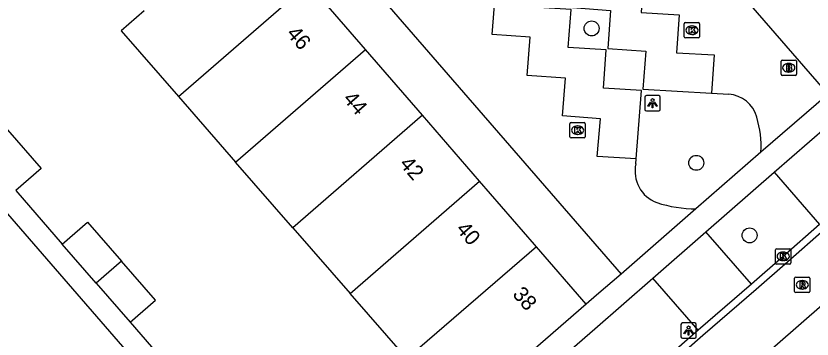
# Model space of a CAD drawing. Extents: x 155888 to 156864, y 383882 to 384671.
# Drawn here: x 156320.3 to 156372.4, y 384088.8 to 384110 of the extents above; entities that cross this region are included whole.
import ezdxf

# ---------------------------------------------------------------- set-up
doc = ezdxf.new("R2010")
doc.units = 0
for name, color, linetype in [('IMGEO_Boom', 7, 'Continuous'), ('IMGEO_Brandkraan', 7, 'Continuous'), ('IMGEO_Kolk', 7, 'Continuous'), ('IMGEO_Lichtpunt', 7, 'Continuous'), ('IMGEO_Pand', 7, 'Continuous'), ('IMGEO_Pand_nummerreeks', 7, 'Continuous'), ('IMGEO_Parkeervlak_open', 7, 'Continuous'), ('IMGEO_Rijbaan_lokaal_gesloten', 7, 'Continuous'), ('IMGEO_Rijbaan_lokaal_open', 7, 'Continuous'), ('IMGEO_Rioolput', 7, 'Continuous'), ('IMGEO_Voetpad_open', 7, 'Continuous')]:
    doc.layers.add(name, color=color, linetype=linetype)

msp = doc.modelspace()

# ---------------------------------------------------------------- linework, layer by layer
at = {"layer": 'IMGEO_Boom'}
for centre in [(156357.971, 384109.154), (156364.816, 384100.364), (156368.307, 384095.623)]:
    msp.add_circle(centre, 0.489, dxfattribs=at)
at = {"layer": 'IMGEO_Brandkraan'}
for p, q in [((156370.445, 384107.086), (156371.297, 384107.086)), ((156370.37, 384106.16), (156370.37, 384107.012)), ((156370.858, 384106.866), (156370.883, 384106.866)), ((156371.371, 384107.012), (156371.371, 384106.16)), ((156371.297, 384106.086), (156370.445, 384106.086)), ((156370.881, 384106.306), (156370.856, 384106.306))]:
    msp.add_line(p, q, dxfattribs=at)
for points in [[(156370.445, 384107.086), (156371.297, 384107.086)], [(156370.37, 384106.16), (156370.37, 384107.012)], [(156370.718, 384106.786), (156370.718, 384106.386), (156370.931, 384106.386)], [(156370.949, 384106.786), (156370.718, 384106.786)], [(156370.897, 384106.705), (156370.843, 384106.705), (156370.843, 384106.629)], [(156370.843, 384106.629), (156370.896, 384106.629)], [(156371.371, 384107.012), (156371.371, 384106.16)], [(156371.297, 384106.086), (156370.445, 384106.086)], [(156370.905, 384106.553), (156370.843, 384106.553), (156370.843, 384106.472)], [(156370.843, 384106.472), (156370.905, 384106.472)]]:
    msp.add_lwpolyline(points, dxfattribs=at)
for centre, radius, start, end in [((156370.447, 384107.01), 0.0765, 91.552, 178.448), ((156370.447, 384107.01), 0.0765, 91.552, 178.448), ((156371.295, 384107.01), 0.0765, 1.552, 88.448), ((156371.295, 384107.01), 0.0765, 1.552, 88.448), ((156370.898, 384106.667), 0.0379, 267.8285, 90.9355), ((156370.953, 384106.641), 0.145, 59.4692, 91.5367), ((156370.978, 384106.688), 0.0922, 285.5137, 58.1501), ((156370.983, 384106.496), 0.105, 301.3115, 78.989), ((156370.447, 384106.162), 0.0765, 181.552, 268.448), ((156370.447, 384106.162), 0.0765, 181.552, 268.448), ((156370.906, 384106.512), 0.0404, 269.8759, 90.5077), ((156370.937, 384106.637), 0.251, 268.6676, 293.5347), ((156371.295, 384106.162), 0.0765, 271.552, 358.448), ((156371.295, 384106.162), 0.0765, 271.552, 358.448)]:
    msp.add_arc(centre, radius, start, end, dxfattribs=at)
for centre, major_axis, ratio, start_param, end_param in [((156370.857, 384106.586), (-0.387, 0.002), 0.722429, 4.712389, 7.853982), ((156370.882, 384106.586), (-0.39, 0.002), 0.717154, 1.570796, 4.712389)]:
    msp.add_ellipse(centre, major_axis=major_axis, ratio=ratio, start_param=start_param, end_param=end_param, dxfattribs=at)
at = {"layer": 'IMGEO_Kolk'}
for p, q in [((156364.036, 384108.614), (156364.036, 384109.466)), ((156364.111, 384109.54), (156364.963, 384109.54)), ((156364.524, 384109.32), (156364.549, 384109.32)), ((156365.037, 384109.466), (156365.037, 384108.614)), ((156364.547, 384108.76), (156364.522, 384108.76)), ((156364.963, 384108.54), (156364.111, 384108.54)), ((156356.552, 384102.075), (156356.552, 384102.927)), ((156356.627, 384103.001), (156357.479, 384103.001)), ((156357.553, 384102.927), (156357.553, 384102.075)), ((156357.04, 384102.781), (156357.065, 384102.781)), ((156357.479, 384102.001), (156356.627, 384102.001)), ((156357.063, 384102.221), (156357.038, 384102.221)), ((156370.008, 384093.821), (156370.008, 384094.673)), ((156370.083, 384094.747), (156370.935, 384094.747)), ((156371.009, 384094.673), (156371.009, 384093.821)), ((156370.496, 384094.527), (156370.521, 384094.527)), ((156370.935, 384093.747), (156370.083, 384093.747)), ((156370.519, 384093.967), (156370.494, 384093.967))]:
    msp.add_line(p, q, dxfattribs=at)
for points in [[(156364.036, 384108.614), (156364.036, 384109.466)], [(156364.111, 384109.54), (156364.963, 384109.54)], [(156364.357, 384109.24), (156364.48, 384109.24), (156364.48, 384109.089), (156364.61, 384109.24), (156364.774, 384109.24), (156364.628, 384109.089), (156364.781, 384108.84), (156364.629, 384108.84), (156364.544, 384109.004), (156364.48, 384108.937), (156364.48, 384108.84), (156364.357, 384108.84), (156364.357, 384109.24)], [(156365.037, 384109.466), (156365.037, 384108.614)], [(156364.963, 384108.54), (156364.111, 384108.54)], [(156356.552, 384102.075), (156356.552, 384102.927)], [(156356.627, 384103.001), (156357.479, 384103.001)], [(156357.553, 384102.927), (156357.553, 384102.075)], [(156356.873, 384102.701), (156356.996, 384102.701), (156356.996, 384102.55), (156357.126, 384102.701), (156357.29, 384102.701), (156357.144, 384102.55), (156357.297, 384102.301), (156357.145, 384102.301), (156357.06, 384102.465), (156356.996, 384102.398), (156356.996, 384102.301), (156356.873, 384102.301), (156356.873, 384102.701)], [(156357.479, 384102.001), (156356.627, 384102.001)], [(156370.008, 384093.821), (156370.008, 384094.673)], [(156370.083, 384094.747), (156370.935, 384094.747)], [(156371.009, 384094.673), (156371.009, 384093.821)], [(156370.329, 384094.447), (156370.452, 384094.447), (156370.452, 384094.296), (156370.582, 384094.447), (156370.746, 384094.447), (156370.6, 384094.296), (156370.753, 384094.047), (156370.601, 384094.047), (156370.516, 384094.211), (156370.452, 384094.144), (156370.452, 384094.047), (156370.329, 384094.047), (156370.329, 384094.447)], [(156370.935, 384093.747), (156370.083, 384093.747)]]:
    msp.add_lwpolyline(points, dxfattribs=at)
for centre, start, end in [((156364.113, 384109.464), 91.552, 178.448), ((156364.113, 384109.464), 91.552, 178.448), ((156364.961, 384109.464), 1.552, 88.448), ((156364.961, 384109.464), 1.552, 88.448), ((156364.113, 384108.616), 181.552, 268.448), ((156364.113, 384108.616), 181.552, 268.448), ((156364.961, 384108.616), 271.552, 358.448), ((156364.961, 384108.616), 271.552, 358.448), ((156356.629, 384102.925), 91.552, 178.448), ((156356.629, 384102.925), 91.552, 178.448), ((156357.477, 384102.925), 1.552, 88.448), ((156357.477, 384102.925), 1.552, 88.448), ((156356.629, 384102.077), 181.552, 268.448), ((156356.629, 384102.077), 181.552, 268.448), ((156357.477, 384102.077), 271.552, 358.448), ((156357.477, 384102.077), 271.552, 358.448), ((156370.085, 384094.671), 91.552, 178.448), ((156370.085, 384094.671), 91.552, 178.448), ((156370.933, 384094.671), 1.552, 88.448), ((156370.933, 384094.671), 1.552, 88.448), ((156370.085, 384093.823), 181.552, 268.448), ((156370.085, 384093.823), 181.552, 268.448), ((156370.933, 384093.823), 271.552, 358.448), ((156370.933, 384093.823), 271.552, 358.448)]:
    msp.add_arc(centre, 0.0765, start, end, dxfattribs=at)
for centre, major_axis, ratio, start_param, end_param in [((156364.523, 384109.04), (-0.387, 0.002), 0.722429, 4.712389, 7.853982), ((156364.548, 384109.04), (-0.39, 0.002), 0.717154, 1.570796, 4.712389), ((156357.039, 384102.501), (-0.387, 0.002), 0.722429, 4.712389, 7.853982), ((156357.064, 384102.501), (-0.39, 0.002), 0.717154, 1.570796, 4.712389), ((156370.495, 384094.247), (-0.387, 0.002), 0.722429, 4.712389, 7.853982), ((156370.52, 384094.247), (-0.39, 0.002), 0.717154, 1.570796, 4.712389)]:
    msp.add_ellipse(centre, major_axis=major_axis, ratio=ratio, start_param=start_param, end_param=end_param, dxfattribs=at)
at = {"layer": 'IMGEO_Lichtpunt'}
for p, q in [((156361.457, 384104.668), (156361.457, 384103.861)), ((156361.457, 384104.668), (156361.457, 384103.861)), ((156362.359, 384104.763), (156361.551, 384104.763)), ((156362.359, 384104.763), (156361.551, 384104.763)), ((156362.453, 384103.861), (156362.453, 384104.668)), ((156362.453, 384103.861), (156362.453, 384104.668)), ((156361.551, 384103.767), (156362.359, 384103.767)), ((156361.551, 384103.767), (156362.359, 384103.767)), ((156364.718, 384089.895), (156363.91, 384089.895)), ((156364.718, 384089.895), (156363.91, 384089.895)), ((156363.816, 384089.8), (156363.816, 384088.993)), ((156363.816, 384089.8), (156363.816, 384088.993)), ((156364.812, 384088.993), (156364.812, 384089.8)), ((156364.812, 384088.993), (156364.812, 384089.8)), ((156363.91, 384088.899), (156364.718, 384088.899)), ((156363.91, 384088.899), (156364.718, 384088.899))]:
    msp.add_line(p, q, dxfattribs=at)
for points in [[(156361.831, 384104.332), (156361.87, 384104.304), (156361.682, 384104.042), (156361.644, 384104.069), (156361.831, 384104.332)], [(156361.933, 384104.284), (156361.98, 384104.284), (156361.98, 384103.962), (156361.933, 384103.962), (156361.933, 384104.284)], [(156362.043, 384104.304), (156362.081, 384104.331), (156362.268, 384104.069), (156362.229, 384104.041), (156362.043, 384104.304)], [(156364.19, 384089.464), (156364.229, 384089.436), (156364.041, 384089.174), (156364.003, 384089.201), (156364.19, 384089.464)], [(156364.292, 384089.416), (156364.339, 384089.416), (156364.339, 384089.094), (156364.292, 384089.094), (156364.292, 384089.416)], [(156364.402, 384089.436), (156364.44, 384089.463), (156364.627, 384089.201), (156364.588, 384089.173), (156364.402, 384089.436)]]:
    msp.add_lwpolyline(points, dxfattribs=at)
for centre in [(156361.956, 384104.466), (156364.315, 384089.598)]:
    msp.add_circle(centre, 0.0994, dxfattribs=at)
for centre, start, end in [((156361.551, 384104.668), 90, 180), ((156361.551, 384104.668), 90, 180), ((156362.359, 384104.668), 0, 90), ((156362.359, 384104.668), 0, 90), ((156361.551, 384103.861), 180, 270), ((156361.551, 384103.861), 180, 270), ((156362.359, 384103.861), 270, 0), ((156362.359, 384103.861), 270, 360), ((156363.91, 384089.8), 90, 180), ((156363.91, 384089.8), 90, 180), ((156364.718, 384089.8), 0, 90), ((156364.718, 384089.8), 0, 90), ((156363.91, 384088.993), 180, 270), ((156363.91, 384088.993), 180, 270), ((156364.718, 384088.993), 270, 0), ((156364.718, 384088.993), 270, 360)]:
    msp.add_arc(centre, 0.0946, start, end, dxfattribs=at)
at = {"layer": 'IMGEO_Pand'}
for points in [[(156330.929, 384104.7), (156339.43, 384112.085)], [(156343.163, 384107.781), (156339.43, 384112.085)], [(156328.695, 384110.304), (156327.186, 384108.993), (156330.929, 384104.7)], [(156334.671, 384100.407), (156343.163, 384107.781)], [(156346.896, 384103.477), (156343.163, 384107.781)], [(156330.929, 384104.7), (156334.671, 384100.407)], [(156346.896, 384103.477), (156338.413, 384096.115)], [(156350.629, 384099.174), (156346.896, 384103.477)], [(156319.75, 384102.532), (156321.949, 384099.997), (156320.29, 384098.559)], [(156338.413, 384096.115), (156334.671, 384100.407)], [(156342.157, 384091.821), (156350.629, 384099.174)], [(156354.362, 384094.871), (156354.231, 384095.022), (156350.629, 384099.174)], [(156323.327, 384095.056), (156324.982, 384096.491), (156327.207, 384093.926)], [(156338.413, 384096.115), (156342.157, 384091.821)], [(156325.552, 384092.489), (156323.326, 384095.055), (156323.327, 384095.056)], [(156354.362, 384094.871), (156344.503, 384086.363)], [(156357.607, 384091.13), (156354.362, 384094.871)], [(156327.207, 384093.926), (156325.552, 384092.489)], [(156327.766, 384089.938), (156329.421, 384091.373), (156327.207, 384093.926)], [(156325.552, 384092.489), (156327.766, 384089.938)], [(156344.503, 384086.363), (156344.387, 384086.497), (156345.757, 384087.691), (156342.157, 384091.821)], [(156357.607, 384091.13), (156347.788, 384082.594)]]:
    msp.add_lwpolyline(points, dxfattribs=at)
at = {"layer": 'IMGEO_Parkeervlak_open'}
for points in [[(156338.388, 384134.355), (156338.204, 384131.817), (156340.769, 384131.604), (156340.601, 384129.142), (156343.099, 384128.952), (156342.894, 384126.475), (156345.377, 384126.289), (156345.204, 384123.82), (156347.688, 384123.622), (156347.496, 384121.14), (156349.992, 384120.94), (156349.791, 384118.488), (156352.291, 384118.271), (156352.1, 384115.84), (156354.592, 384115.641), (156354.408, 384113.168), (156356.916, 384112.984), (156356.726, 384110.521), (156359.215, 384110.326), (156359.026, 384107.845), (156361.521, 384107.677), (156361.324, 384105.188), (156365.822, 384104.918)], [(156360.883, 384100.625), (156361.227, 384105.088), (156358.744, 384105.253), (156358.925, 384107.753), (156356.428, 384107.91), (156356.631, 384110.385), (156354.125, 384110.551), (156354.291, 384113.051), (156351.812, 384113.225), (156351.999, 384115.72), (156349.505, 384115.866), (156349.704, 384118.366), (156347.213, 384118.534), (156347.391, 384121.03), (156344.909, 384121.211), (156345.089, 384123.687), (156342.615, 384123.85), (156342.773, 384126.347), (156340.309, 384126.506), (156340.489, 384129.019), (156337.995, 384129.181), (156338.194, 384131.681), (156335.585, 384131.929)]]:
    msp.add_lwpolyline(points, dxfattribs=at)
at = {"layer": 'IMGEO_Rijbaan_lokaal_gesloten'}
for points in [[(156424.267, 384128.023), (156420.432, 384132.447), (156418.135, 384135.097), (156376.676, 384098.955), (156373.188, 384095.976), (156370.811, 384093.901), (156368.728, 384092.09), (156365.252, 384089.08), (156333.957, 384061.613), (156326.458, 384055.98), (156326.022, 384055.616)], [(156327.105, 384050.098), (156331.018, 384054.386), (156412.184, 384125.247), (156412.191, 384125.253)]]:
    msp.add_lwpolyline(points, dxfattribs=at)
at = {"layer": 'IMGEO_Rijbaan_lokaal_open'}
for points in [[(156373.448, 384104.867), (156340.225, 384143.101)], [(156338.388, 384134.355), (156342.962, 384134.093), (156342.789, 384131.469), (156345.261, 384131.289), (156345.041, 384128.838), (156347.532, 384128.639), (156347.368, 384126.167), (156349.866, 384125.986), (156349.688, 384123.489), (156352.192, 384123.315), (156352.008, 384120.848), (156354.471, 384120.649), (156354.294, 384118.2), (156356.762, 384117.993), (156356.616, 384115.508), (156359.083, 384115.333), (156358.906, 384112.815), (156361.394, 384112.686), (156361.202, 384110.195), (156363.698, 384110.045), (156363.527, 384107.557), (156366, 384107.436), (156365.822, 384104.918)], [(156360.883, 384100.625), (156358.341, 384100.78), (156358.548, 384103.254), (156356.069, 384103.439), (156356.27, 384105.911), (156353.761, 384106.087), (156353.942, 384108.574), (156351.453, 384108.752), (156351.657, 384111.239), (156349.168, 384111.423), (156349.353, 384113.885), (156346.864, 384114.068), (156347.035, 384116.548), (156344.594, 384116.735), (156344.761, 384119.246), (156342.281, 384119.373), (156342.439, 384121.883), (156339.969, 384122.064), (156340.128, 384124.539), (156337.659, 384124.724), (156337.853, 384127.216), (156335.256, 384127.393), (156335.585, 384131.929)], [(156326.654, 384131.386), (156359.895, 384093.079)], [(156365.822, 384104.918), (156366.943, 384104.851)], [(156373.448, 384104.867), (156369.05, 384101.069)], [(156369.92, 384099.753), (156373.38, 384102.774)], [(156360.866, 384100.295), (156360.883, 384100.625)], [(156369.92, 384099.753), (156372.888, 384096.324)], [(156364.8, 384097.36), (156359.895, 384093.079)], [(156372.888, 384096.324), (156370.508, 384094.247), (156368.427, 384092.437)], [(156361.976, 384092.817), (156365.454, 384095.854)], [(156368.427, 384092.437), (156365.454, 384095.854)], [(156364.949, 384089.426), (156361.976, 384092.817)], [(156368.427, 384092.437), (156364.949, 384089.426)], [(156364.949, 384089.426), (156333.68, 384061.98), (156326.165, 384056.335)]]:
    msp.add_lwpolyline(points, dxfattribs=at)
for centre, radius, start, end in [((156366.792, 384102.79), 2.066, 15.9236, 85.8042), ((156362.323, 384101.432), 6.737, 356.9088, 16.601), ((156362.982, 384099.808), 2.171, 167.0414, 250.0779), ((156364.808, 384105.652), 8.292, 251.9736, 269.9455)]:
    msp.add_arc(centre, radius, start, end, dxfattribs=at)
at = {"layer": 'IMGEO_Rioolput'}
for p, q in [((156371.256, 384091.96), (156371.256, 384092.812)), ((156371.331, 384092.886), (156372.183, 384092.886)), ((156371.744, 384092.666), (156371.769, 384092.666)), ((156372.257, 384092.812), (156372.257, 384091.96)), ((156371.767, 384092.106), (156371.742, 384092.106)), ((156372.183, 384091.886), (156371.331, 384091.886))]:
    msp.add_line(p, q, dxfattribs=at)
for points in [[(156371.256, 384091.96), (156371.256, 384092.812)], [(156371.331, 384092.886), (156372.183, 384092.886)], [(156371.845, 384092.584), (156371.593, 384092.586), (156371.593, 384092.186)], [(156371.771, 384092.505), (156371.717, 384092.505), (156371.717, 384092.424)], [(156372.257, 384092.812), (156372.257, 384091.96)], [(156371.593, 384092.186), (156371.717, 384092.186), (156371.717, 384092.348), (156371.728, 384092.348)], [(156371.717, 384092.424), (156371.769, 384092.424)], [(156371.775, 384092.319), (156371.846, 384092.186), (156371.986, 384092.186), (156371.921, 384092.312)], [(156372.183, 384091.886), (156371.331, 384091.886)]]:
    msp.add_lwpolyline(points, dxfattribs=at)
for centre, radius, start, end in [((156371.333, 384092.81), 0.0765, 91.552, 178.448), ((156371.333, 384092.81), 0.0765, 91.552, 178.448), ((156371.777, 384092.409), 0.0964, 77.0061, 93.1865), ((156371.791, 384092.466), 0.0378, 276.6634, 79.6772), ((156371.844, 384092.474), 0.109, 350.3612, 89.416), ((156372.181, 384092.81), 0.0765, 1.552, 88.448), ((156372.181, 384092.81), 0.0765, 1.552, 88.448), ((156371.727, 384092.295), 0.0533, 26.0293, 88.6989), ((156371.753, 384092.613), 0.19, 274.7715, 282.9687), ((156371.842, 384092.474), 0.112, 277.5842, 350.9817), ((156371.826, 384092.259), 0.108, 29.5134, 73.7905), ((156371.333, 384091.962), 0.0765, 181.552, 268.448), ((156371.333, 384091.962), 0.0765, 181.552, 268.448), ((156372.181, 384091.962), 0.0765, 271.552, 358.448), ((156372.181, 384091.962), 0.0765, 271.552, 358.448)]:
    msp.add_arc(centre, radius, start, end, dxfattribs=at)
for centre, major_axis, ratio, start_param, end_param in [((156371.743, 384092.386), (-0.387, 0.002), 0.722429, 4.712389, 7.853982), ((156371.768, 384092.386), (-0.39, 0.002), 0.717154, 1.570796, 4.712389)]:
    msp.add_ellipse(centre, major_axis=major_axis, ratio=ratio, start_param=start_param, end_param=end_param, dxfattribs=at)
at = {"layer": 'IMGEO_Voetpad_open'}
for points in [[(156338.946, 384074.921), (156305.662, 384113.279)], [(156369.05, 384101.069), (156364.8, 384097.36)], [(156365.454, 384095.854), (156369.92, 384099.753)], [(156320.29, 384098.559), (156323.327, 384095.056)], [(156359.895, 384093.079), (156358.294, 384091.715), (156357.607, 384091.13)], [(156320.966, 384057.246), (156358.182, 384089.505), (156361.976, 384092.817)], [(156327.766, 384089.938), (156330.842, 384086.39)]]:
    msp.add_lwpolyline(points, dxfattribs=at)

# ---------------------------------------------------------------- texts
at = {"layer": 'IMGEO_Pand_nummerreeks'}
for s, p in [('46', (156337.952, 384108.784)), ('44', (156341.649, 384104.522)), ('42', (156345.344, 384100.263)), ('40', (156349.045, 384095.996)), ('38', (156352.742, 384091.734))]:
    msp.add_text(s, height=1, rotation=310.9395, dxfattribs=at).set_placement(p)

doc.saveas('drawing.dxf')
